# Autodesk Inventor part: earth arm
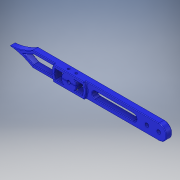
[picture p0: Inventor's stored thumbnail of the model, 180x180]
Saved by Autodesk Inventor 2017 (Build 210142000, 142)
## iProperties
Created: 2016-05
Part Number: earth arm
Material: Generic
Document SubType Name: Modeling
Designer: Stan
Density: 1 g/cm^3
Appearance: Blue - Wall Paint - Glossy
Mass: 41.1263 g
Surface Area: 188.014 cm^2
Volume: 41.1263 cm^3
Author: Stan
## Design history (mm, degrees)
sketch "Sketch1"
  geometry: L1 (-63.469, 12.7)-(147.32, 12.7); L2 (147.32, -12.7)-(-63.469, -12.7); L3 (-62.051, 7.62)-(-27.456, 7.62); L4 (-27.456, -7.62)-(-62.051, -7.62); C1 r 2.778 at (0, 0); C2 r 3.175 at (147.32, 0); C3 r 3.175 at (127.508, 0); A1 r 12.7 centre (147.32, 0) between (147.32, -12.7) and (147.32, 12.7); A2 r 87.876 centre (-109.572, 87.511) between (-101.569, 0) and (-63.469, 12.7); A3 r 87.876 centre (-109.572, -87.511) between (-63.469, -12.7) and (-101.569, 0); A4 r 92.956 centre (-109.572, -87.511) between (-62.051, -7.62) and (-78.224, 0); A5 r 92.956 centre (-109.572, 87.511) between (-78.224, 0) and (-62.051, 7.62); A6 r 28.494 centre (0, 0) between (-27.456, 7.62) and (-27.456, -7.62); 2 further points
  constraints: 12 point on circle, 9 centre point, 8 end point, 3 coincident, 4 other
  dimensions: "d6" = 5.55625 diameter of C1; "d7" = 12.7 radius of A1; "d21" = 38.1 horizontal distance of L1.start point (-101.569, 0); "d23" = 5.08 distance between parallel lines of L1 L3; "d25" = 34.59498 distance of L3.start L3.end; "d26" = 34.59498 distance of L4.start L4.end; "d27" = 28.49363 radius of A6; "d28" = 15.24 distance between parallel lines of L4 L3; "d29" = 50.76862 horizontal distance of L3.end A4.end; "d30" = 5.08 radial gap between concentric circles of A3 A4; "d62" = 6.35 diameter of C2; "d71" = 147.32 distance of A1.centre point (0, 0); "d72" = 25.4 distance between parallel lines of L2 L1; "d73" = 6.35 diameter of C3; "d74" = 19.812 distance of C3.centre A1.centre
workplane "Work Plane7"
sketch "Sketch6"
  geometry: L1 (41.275, 5.603)-(104.775, 5.603); L2 (41.275, -5.603)-(104.775, -5.603); A1 r 5.603 centre (41.275, 0) between (41.275, 5.603) and (41.275, -5.603); A2 r 5.603 centre (104.775, 0) between (104.775, -5.603) and (104.775, 5.603); 1 further point
  constraints: 4 end point, 4 point on circle, 2 centre point, 2 tangent
  dimensions: "d80" = 63.5 distance of A2.centre A1.centre
extrude "Extrusion15" join sketch "Sketch1" distance "d75" = 9.525; taper "d76" = 0 deg
sketch "Sketch8"
  geometry: L1 (-63.469, 12.7)-(147.32, 12.7) reference; L2 (-25.507, 12.7)-(25.507, 12.7); L3 (147.32, -12.7)-(-63.469, -12.7) reference; L4 (-25.507, -12.7)-(25.507, -12.7); C1 r 2.778 at (0, 0) reference; A1 r 28.494 centre (0, 0) between (25.507, -12.7) and (25.507, 12.7); A2 r 28.494 centre (0, 0) between (-25.507, 12.7) and (-25.507, -12.7); 1 further point
  constraints: 4 end point, 4 point on circle, 4 point on line, 2 centre point, 1 coincident
extrude "Extrusion17" join sketch "Sketch8" distance "d81" = 3.175; taper "d82" = 0 deg
sketch "Sketch9"
  geometry: L1 (-22.56, 7.62)-(-10.16, 7.62); L2 (-22.56, -7.62)-(-10.16, -7.62); L3 (10.16, -7.62)-(22.56, -7.62); L4 (10.16, 7.62)-(22.56, 7.62); A1 r 12.7 centre (0, 0) between (10.16, -7.62) and (10.16, 7.62); A2 r 12.7 centre (0, 0) between (-10.16, 7.62) and (-10.16, -7.62); A3 r 23.812 centre (0, 0) between (-22.56, 7.62) and (-22.56, -7.62); A4 r 23.812 centre (0, 0) between (22.56, -7.62) and (22.56, 7.62); 3 further points
  constraints: 8 end point, 8 point on circle, 4 centre point, 4 point on line, 2 coincident, 1 horizontal, 1 parallel
extrude "Extrusion18" cut sketch "Sketch9" distance "d84" = 12.7; taper "d85" = 0 deg
sketch "Sketch10"
  geometry: L1 (-14.287, 0.508)-(14.287, 0.508); L2 (14.287, 0.508)-(14.287, -0.508); L3 (14.287, -0.508)-(-14.287, -0.508); L4 (-14.287, -0.508)-(-14.287, 0.508); 1 further point
  constraints: 8 end point, 2 parallel, 1 horizontal, 1 perpendicular
  dimensions: "d86" = 1.016 distance between parallel lines of L3 L1; "d87" = 0.508 distance from line of L3 point (0, 0); "d88" = 14.2875 distance from line of L4 point (0, 0); "d89" = 14.2875 distance from line of point (0, 0) L2
extrude "Extrusion19" cut sketch "Sketch10" distance "d90" = 12.7; taper "d91" = 0 deg
sketch "Sketch11"
  geometry: L1 (53.309, -12.7)-(53.309, 0) reference; L2 (0, 0)-(210.789, 0) reference; C1 r 1.905 at (57.119, -6.35); C2 r 1.905 at (69.819, -6.35); 1 further point
  constraints: 2 centre point
  dimensions: "d92" = 3.81 diameter of C1; "d93" = 3.81 diameter of C2; "d94" = 12.7 distance of C2.centre C1.centre; "d95" = 3.81 distance from line of C1.centre L1; "d96" = 6.35 distance from line of L2 C2.centre; "d97" = 6.35 distance from line of L2 C1.centre
extrude "Extrusion20" cut sketch "Sketch11" distance "d98" = 25.4; taper "d99" = 0 deg
extrude "Extrusion21" cut sketch "Sketch6" distance "d100" = 9.525; taper "d101" = 0 deg
fillet "Fillet1" dims "d102" = 0.79375
fillet "Fillet2" dims "d103" = 0.79375
fillet "Fillet3" dims "d104" = 0.79375
fillet "Fillet4" dims "d105" = 0.79375
body "Solid6"
other parameters: "d83" = 47.625
